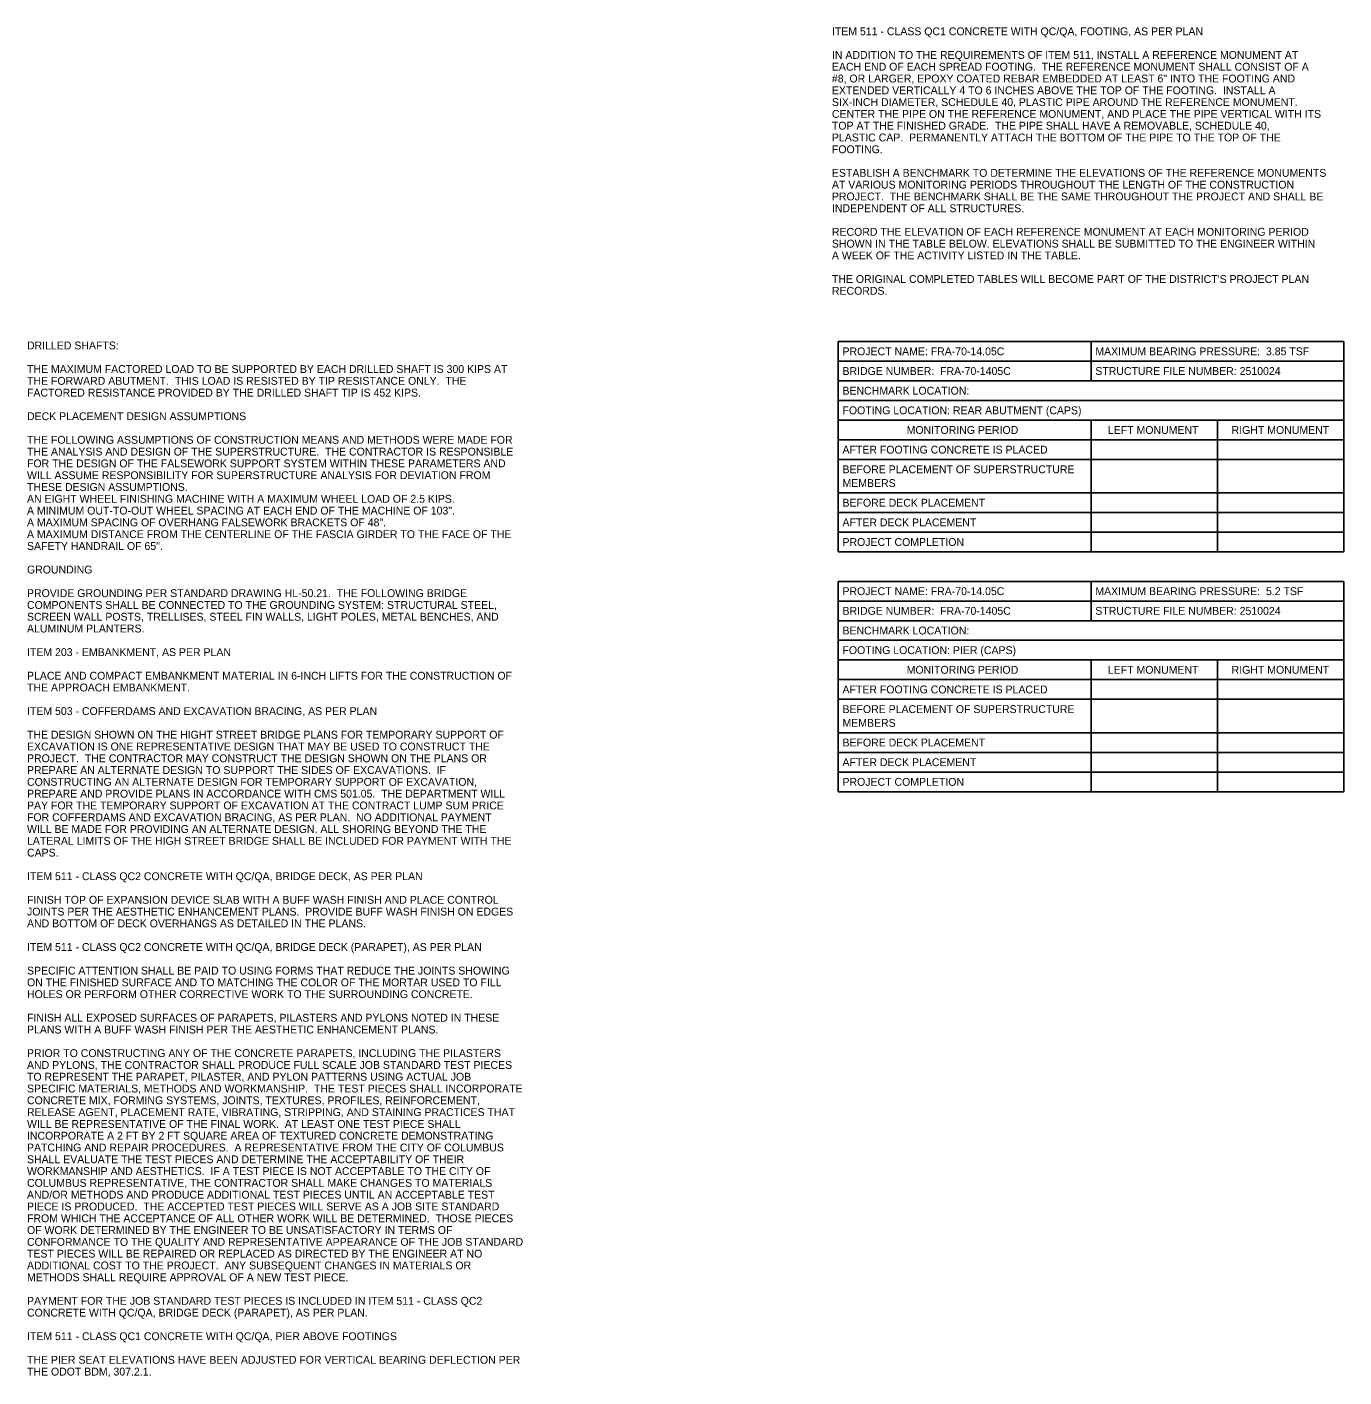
# Model space of a CAD drawing. Extents: x -27.4 to 41.5, y -43.2 to 24.4.
# Drawn here: x -27.42 to -3.98, y 0.32 to 24.36 of the extents above; entities that cross this region are included whole.
import ezdxf

# ---------------------------------------------------------------- set-up
doc = ezdxf.new("R2010")
doc.units = 0
doc.layers.add('BR_P_Sub_Foot_Hidden', color=7, linetype='Continuous')

msp = doc.modelspace()

# ---------------------------------------------------------------- linework, layer by layer
at = {"layer": 'BR_P_Sub_Foot_Hidden'}
for p, q in [((-12.978, 18.759), (-3.978, 18.759)), ((-12.978, 18.759), (-12.978, 15.014)), ((-8.478, 18.759), (-8.478, 18.059)), ((-3.978, 18.759), (-3.978, 15.014)), ((-12.978, 18.409), (-3.978, 18.409)), ((-12.978, 18.059), (-3.978, 18.059)), ((-12.978, 17.709), (-3.978, 17.709)), ((-12.978, 17.359), (-3.978, 17.359)), ((-8.478, 17.359), (-8.478, 15.014)), ((-6.228, 17.359), (-6.228, 15.014)), ((-12.978, 17.009), (-3.978, 17.009)), ((-12.978, 16.659), (-3.978, 16.659)), ((-12.978, 16.064), (-3.978, 16.064)), ((-12.978, 15.714), (-3.978, 15.714)), ((-12.978, 15.364), (-3.978, 15.364)), ((-12.978, 15.014), (-3.978, 15.014)), ((-12.978, 14.489), (-3.978, 14.489)), ((-12.978, 14.489), (-12.978, 10.744)), ((-8.478, 14.489), (-8.478, 13.789)), ((-3.978, 14.489), (-3.978, 10.744)), ((-12.978, 14.139), (-3.978, 14.139)), ((-12.978, 13.789), (-3.978, 13.789)), ((-12.978, 13.439), (-3.978, 13.439)), ((-12.978, 13.089), (-3.978, 13.089)), ((-8.478, 13.089), (-8.478, 10.744)), ((-6.228, 13.089), (-6.228, 10.744)), ((-12.978, 12.739), (-3.978, 12.739)), ((-12.978, 12.389), (-3.978, 12.389)), ((-12.978, 11.794), (-3.978, 11.794)), ((-12.978, 11.444), (-3.978, 11.444)), ((-12.978, 11.094), (-3.978, 11.094)), ((-12.978, 10.744), (-3.978, 10.744))]:
    msp.add_line(p, q, dxfattribs=at)

# ---------------------------------------------------------------- texts
for s, p in [('ITEM 511 - CLASS QC1 CONCRETE WITH QC/QA, FOOTING, AS PER PLAN', (-13.092, 24.212)), ('ITEM 511 - CLASS QC1 CONCRETE WITH QC/QA, FOOTING, AS PER PLAN', (-13.092, 24.212)), ('IN ADDITION TO THE REQUIREMENTS OF ITEM 511, INSTALL A REFERENCE MONUMENT AT ', (-13.092, 23.792)), ('EACH END OF EACH SPREAD FOOTING.  THE REFERENCE MONUMENT SHALL CONSIST OF A ', (-13.092, 23.582)), ('#8, OR LARGER, EPOXY COATED REBAR EMBEDDED AT LEAST 6" INTO THE FOOTING AND ', (-13.092, 23.372)), ('SIX-INCH DIAMETER, SCHEDULE 40, PLASTIC PIPE AROUND THE REFERENCE MONUMENT.  ', (-13.092, 22.952)), ('EXTENDED VERTICALLY 4 TO 6 INCHES ABOVE THE TOP OF THE FOOTING.  INSTALL A ', (-13.092, 23.162)), ('CENTER THE PIPE ON THE REFERENCE MONUMENT, AND PLACE THE PIPE VERTICAL WITH ITS ', (-13.092, 22.742)), ('TOP AT THE FINISHED GRADE.  THE PIPE SHALL HAVE A REMOVABLE, SCHEDULE 40, ', (-13.092, 22.532)), ('PLASTIC CAP.  PERMANENTLY ATTACH THE BOTTOM OF THE PIPE TO THE TOP OF THE ', (-13.092, 22.322)), ('FOOTING.', (-13.092, 22.112)), ('ESTABLISH A BENCHMARK TO DETERMINE THE ELEVATIONS OF THE REFERENCE MONUMENTS ', (-13.092, 21.692)), ('AT VARIOUS MONITORING PERIODS THROUGHOUT THE LENGTH OF THE CONSTRUCTION ', (-13.092, 21.482)), ('PROJECT.  THE BENCHMARK SHALL BE THE SAME THROUGHOUT THE PROJECT AND SHALL BE ', (-13.092, 21.272)), ('INDEPENDENT OF ALL STRUCTURES.', (-13.092, 21.062)), ('RECORD THE ELEVATION OF EACH REFERENCE MONUMENT AT EACH MONITORING PERIOD ', (-13.092, 20.642)), ('SHOWN IN THE TABLE BELOW. ELEVATIONS SHALL BE SUBMITTED TO THE ENGINEER WITHIN ', (-13.092, 20.432)), ('A WEEK OF THE ACTIVITY LISTED IN THE TABLE.', (-13.092, 20.222)), ("THE ORIGINAL COMPLETED TABLES WILL BECOME PART OF THE DISTRICT'S PROJECT PLAN ", (-13.092, 19.802)), ('RECORDS.', (-13.092, 19.592)), ('DRILLED SHAFTS:', (-27.419, 18.619)), ('DRILLED SHAFTS:', (-27.419, 18.619)), ('PROJECT NAME: FRA-70-14.05C', (-12.904, 18.514)), ('MAXIMUM BEARING PRESSURE:  3.85 TSF', (-8.404, 18.514)), ('THE MAXIMUM FACTORED LOAD TO BE SUPPORTED BY EACH DRILLED SHAFT IS 300 KIPS AT ', (-27.419, 18.199)), ('BRIDGE NUMBER:  FRA-70-1405C', (-12.904, 18.164)), ('STRUCTURE FILE NUMBER: 2510024', (-8.404, 18.164)), ('THE FORWARD ABUTMENT.  THIS LOAD IS RESISTED BY TIP RESISTANCE ONLY.  THE ', (-27.419, 17.989)), ('FACTORED RESISTANCE PROVIDED BY THE DRILLED SHAFT TIP IS 452 KIPS.', (-27.419, 17.779)), ('BENCHMARK LOCATION:', (-12.904, 17.814)), ('FOOTING LOCATION: REAR ABUTMENT (CAPS)', (-12.904, 17.464)), ('DECK PLACEMENT DESIGN ASSUMPTIONS', (-27.419, 17.359)), ('DECK PLACEMENT DESIGN ASSUMPTIONS', (-27.419, 17.359)), ('THE FOLLOWING ASSUMPTIONS OF CONSTRUCTION MEANS AND METHODS WERE MADE FOR ', (-27.419, 16.939)), ('MONITORING PERIOD', (-11.762, 17.114)), ('LEFT MONUMENT', (-8.18, 17.114)), ('RIGHT MONUMENT', (-5.978, 17.114)), ('THE ANALYSIS AND DESIGN OF THE SUPERSTRUCTURE.  THE CONTRACTOR IS RESPONSIBLE ', (-27.419, 16.729)), ('AFTER FOOTING CONCRETE IS PLACED', (-12.904, 16.764)), ('FOR THE DESIGN OF THE FALSEWORK SUPPORT SYSTEM WITHIN THESE PARAMETERS AND ', (-27.419, 16.519)), ('WILL ASSUME RESPONSIBILITY FOR SUPERSTRUCTURE ANALYSIS FOR DEVIATION FROM ', (-27.419, 16.309)), ('BEFORE PLACEMENT OF SUPERSTRUCTURE', (-12.904, 16.414)), ('THESE DESIGN ASSUMPTIONS.', (-27.419, 16.099)), ('MEMBERS', (-12.904, 16.169)), ('AN EIGHT WHEEL FINISHING MACHINE WITH A MAXIMUM WHEEL LOAD OF 2.5 KIPS.', (-27.419, 15.889)), ('BEFORE DECK PLACEMENT', (-12.904, 15.819)), ('A MINIMUM OUT-TO-OUT WHEEL SPACING AT EACH END OF THE MACHINE OF 103".', (-27.419, 15.679)), ('A MAXIMUM SPACING OF OVERHANG FALSEWORK BRACKETS OF 48".', (-27.419, 15.469)), ('A MAXIMUM DISTANCE FROM THE CENTERLINE OF THE FASCIA GIRDER TO THE FACE OF THE ', (-27.419, 15.259)), ('AFTER DECK PLACEMENT', (-12.904, 15.469)), ('SAFETY HANDRAIL OF 65".', (-27.419, 15.049)), ('PROJECT COMPLETION', (-12.904, 15.119)), ('GROUNDING', (-27.419, 14.629)), ('GROUNDING', (-27.419, 14.629)), ('PROVIDE GROUNDING PER STANDARD DRAWING HL-50.21.  THE FOLLOWING BRIDGE ', (-27.419, 14.209)), ('PROJECT NAME: FRA-70-14.05C', (-12.904, 14.244)), ('MAXIMUM BEARING PRESSURE:  5.2 TSF', (-8.404, 14.244)), ('COMPONENTS SHALL BE CONNECTED TO THE GROUNDING SYSTEM: STRUCTURAL STEEL, ', (-27.419, 13.999)), ('BRIDGE NUMBER:  FRA-70-1405C', (-12.904, 13.894)), ('STRUCTURE FILE NUMBER: 2510024', (-8.404, 13.894)), ('ALUMINUM PLANTERS.', (-27.419, 13.579)), ('SCREEN WALL POSTS, TRELLISES, STEEL FIN WALLS, LIGHT POLES, METAL BENCHES, AND ', (-27.419, 13.789)), ('BENCHMARK LOCATION:', (-12.904, 13.544)), ('ITEM 203 - EMBANKMENT, AS PER PLAN', (-27.419, 13.159)), ('ITEM 203 - EMBANKMENT, AS PER PLAN', (-27.419, 13.159)), ('FOOTING LOCATION: PIER (CAPS)', (-12.904, 13.194)), ('MONITORING PERIOD', (-11.762, 12.844)), ('LEFT MONUMENT', (-8.18, 12.844)), ('RIGHT MONUMENT', (-5.978, 12.844)), ('PLACE AND COMPACT EMBANKMENT MATERIAL IN 6-INCH LIFTS FOR THE CONSTRUCTION OF ', (-27.419, 12.739)), ('THE APPROACH EMBANKMENT.', (-27.419, 12.529)), ('AFTER FOOTING CONCRETE IS PLACED', (-12.904, 12.494)), ('BEFORE PLACEMENT OF SUPERSTRUCTURE', (-12.904, 12.144)), ('ITEM 503 - COFFERDAMS AND EXCAVATION BRACING, AS PER PLAN', (-27.419, 12.109)), ('ITEM 503 - COFFERDAMS AND EXCAVATION BRACING, AS PER PLAN', (-27.419, 12.109)), ('MEMBERS', (-12.904, 11.899)), ('THE DESIGN SHOWN ON THE HIGHT STREET BRIDGE PLANS FOR TEMPORARY SUPPORT OF ', (-27.419, 11.689)), ('EXCAVATION IS ONE REPRESENTATIVE DESIGN THAT MAY BE USED TO CONSTRUCT THE ', (-27.419, 11.479)), ('BEFORE DECK PLACEMENT', (-12.904, 11.549)), ('PROJECT.  THE CONTRACTOR MAY CONSTRUCT THE DESIGN SHOWN ON THE PLANS OR ', (-27.419, 11.269)), ('AFTER DECK PLACEMENT', (-12.904, 11.199)), ('PREPARE AN ALTERNATE DESIGN TO SUPPORT THE SIDES OF EXCAVATIONS.  IF ', (-27.419, 11.059)), ('CONSTRUCTING AN ALTERNATE DESIGN FOR TEMPORARY SUPPORT OF EXCAVATION, ', (-27.419, 10.849)), ('PROJECT COMPLETION', (-12.904, 10.849)), ('PREPARE AND PROVIDE PLANS IN ACCORDANCE WITH CMS 501.05.  THE DEPARTMENT WILL ', (-27.419, 10.639)), ('PAY FOR THE TEMPORARY SUPPORT OF EXCAVATION AT THE CONTRACT LUMP SUM PRICE ', (-27.419, 10.429)), ('FOR COFFERDAMS AND EXCAVATION BRACING, AS PER PLAN.  NO ADDITIONAL PAYMENT ', (-27.419, 10.219)), ('WILL BE MADE FOR PROVIDING AN ALTERNATE DESIGN. ALL SHORING BEYOND THE THE ', (-27.419, 10.009)), ('LATERAL LIMITS OF THE HIGH STREET BRIDGE SHALL BE INCLUDED FOR PAYMENT WITH THE ', (-27.419, 9.799)), ('CAPS.', (-27.419, 9.589)), ('ITEM 511 - CLASS QC2 CONCRETE WITH QC/QA, BRIDGE DECK, AS PER PLAN', (-27.419, 9.169)), ('ITEM 511 - CLASS QC2 CONCRETE WITH QC/QA, BRIDGE DECK, AS PER PLAN', (-27.419, 9.169)), ('JOINTS PER THE AESTHETIC ENHANCEMENT PLANS.  PROVIDE BUFF WASH FINISH ON EDGES ', (-27.419, 8.539)), ('FINISH TOP OF EXPANSION DEVICE SLAB WITH A BUFF WASH FINISH AND PLACE CONTROL ', (-27.419, 8.749)), ('AND BOTTOM OF DECK OVERHANGS AS DETAILED IN THE PLANS.', (-27.419, 8.329)), ('ITEM 511 - CLASS QC2 CONCRETE WITH QC/QA, BRIDGE DECK (PARAPET), AS PER PLAN', (-27.419, 7.909)), ('ITEM 511 - CLASS QC2 CONCRETE WITH QC/QA, BRIDGE DECK (PARAPET), AS PER PLAN', (-27.419, 7.909)), ('SPECIFIC ATTENTION SHALL BE PAID TO USING FORMS THAT REDUCE THE JOINTS SHOWING ', (-27.419, 7.489)), ('ON THE FINISHED SURFACE AND TO MATCHING THE COLOR OF THE MORTAR USED TO FILL ', (-27.419, 7.279)), ('HOLES OR PERFORM OTHER CORRECTIVE WORK TO THE SURROUNDING CONCRETE.', (-27.419, 7.069)), ('FINISH ALL EXPOSED SURFACES OF PARAPETS, PILASTERS AND PYLONS NOTED IN THESE ', (-27.419, 6.649)), ('PLANS WITH A BUFF WASH FINISH PER THE AESTHETIC ENHANCEMENT PLANS.', (-27.419, 6.439)), ('PRIOR TO CONSTRUCTING ANY OF THE CONCRETE PARAPETS, INCLUDING THE PILASTERS ', (-27.419, 6.019)), ('AND PYLONS, THE CONTRACTOR SHALL PRODUCE FULL SCALE JOB STANDARD TEST PIECES ', (-27.419, 5.809)), ('TO REPRESENT THE PARAPET, PILASTER, AND PYLON PATTERNS USING ACTUAL JOB ', (-27.419, 5.599)), ('SPECIFIC MATERIALS, METHODS AND WORKMANSHIP.  THE TEST PIECES SHALL INCORPORATE ', (-27.419, 5.389)), ('CONCRETE MIX, FORMING SYSTEMS, JOINTS, TEXTURES, PROFILES, REINFORCEMENT, ', (-27.419, 5.179)), ('RELEASE AGENT, PLACEMENT RATE, VIBRATING, STRIPPING, AND STAINING PRACTICES THAT ', (-27.419, 4.969)), ('WILL BE REPRESENTATIVE OF THE FINAL WORK.  AT LEAST ONE TEST PIECE SHALL ', (-27.419, 4.759)), ('INCORPORATE A 2 FT BY 2 FT SQUARE AREA OF TEXTURED CONCRETE DEMONSTRATING ', (-27.419, 4.549)), ('PATCHING AND REPAIR PROCEDURES.  A REPRESENTATIVE FROM THE CITY OF COLUMBUS ', (-27.419, 4.339)), ('SHALL EVALUATE THE TEST PIECES AND DETERMINE THE ACCEPTABILITY OF THEIR ', (-27.419, 4.129)), ('WORKMANSHIP AND AESTHETICS.  IF A TEST PIECE IS NOT ACCEPTABLE TO THE CITY OF ', (-27.419, 3.919)), ('COLUMBUS REPRESENTATIVE, THE CONTRACTOR SHALL MAKE CHANGES TO MATERIALS ', (-27.419, 3.709)), ('AND/OR METHODS AND PRODUCE ADDITIONAL TEST PIECES UNTIL AN ACCEPTABLE TEST ', (-27.419, 3.499)), ('PIECE IS PRODUCED.  THE ACCEPTED TEST PIECES WILL SERVE AS A JOB SITE STANDARD ', (-27.419, 3.289)), ('FROM WHICH THE ACCEPTANCE OF ALL OTHER WORK WILL BE DETERMINED.  THOSE PIECES ', (-27.419, 3.079)), ('OF WORK DETERMINED BY THE ENGINEER TO BE UNSATISFACTORY IN TERMS OF ', (-27.419, 2.869)), ('CONFORMANCE TO THE QUALITY AND REPRESENTATIVE APPEARANCE OF THE JOB STANDARD ', (-27.419, 2.659)), ('TEST PIECES WILL BE REPAIRED OR REPLACED AS DIRECTED BY THE ENGINEER AT NO ', (-27.419, 2.449)), ('ADDITIONAL COST TO THE PROJECT.  ANY SUBSEQUENT CHANGES IN MATERIALS OR ', (-27.419, 2.239)), ('METHODS SHALL REQUIRE APPROVAL OF A NEW TEST PIECE.', (-27.419, 2.029)), ('PAYMENT FOR THE JOB STANDARD TEST PIECES IS INCLUDED IN ITEM 511 - CLASS QC2 ', (-27.419, 1.609)), ('CONCRETE WITH QC/QA, BRIDGE DECK (PARAPET), AS PER PLAN.', (-27.419, 1.399)), ('ITEM 511 - CLASS QC1 CONCRETE WITH QC/QA, PIER ABOVE FOOTINGS', (-27.419, 0.979)), ('ITEM 511 - CLASS QC1 CONCRETE WITH QC/QA, PIER ABOVE FOOTINGS', (-27.419, 0.979)), ('THE PIER SEAT ELEVATIONS HAVE BEEN ADJUSTED FOR VERTICAL BEARING DEFLECTION PER ', (-27.419, 0.559)), ('THE ODOT BDM, 307.2.1.', (-27.419, 0.349))]:
    msp.add_text(s, height=0.14, dxfattribs=at).set_placement(p)

doc.saveas('drawing.dxf')
